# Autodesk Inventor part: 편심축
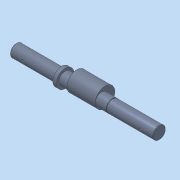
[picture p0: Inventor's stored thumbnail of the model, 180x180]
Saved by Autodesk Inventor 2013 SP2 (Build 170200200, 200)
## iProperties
Manager: 한국ATC센터
Company: 한국ATC센터
Created: 2014-10
Part Number: 편심축
Document SubType Name: Modeling
Designer: 한국ATC센터
Density: 7.86 g/cm^3
Material: 강, 연강
Mass: 1420.77 g
Surface Area: 286.549 cm^2
Volume: 180.76 cm^3
Author: KYOUNG IL JANG
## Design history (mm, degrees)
sketch "스케치1"
  geometry: L1 (-142, 0)-(142, 0); L2 (-142, 0)-(-142, 12.5); L3 (-142, 12.5)-(-52, 12.5); L4 (-52, 12.5)-(-52, 17.5); L5 (-52, 17.5)-(-45, 17.5); L6 (-45, 17.5)-(-45, 12.5); L7 (-45, 12.5)-(48.65, 12.5); L8 (48.65, 12.5)-(48.65, 11.95); L9 (48.65, 11.95)-(50, 11.95); L10 (50, 11.95)-(50, 12.5); L11 (50, 12.5)-(142, 12.5); L12 (142, 12.5)-(142, 0); L13 (109, 12.5)-(109, 9.1); L14 (109, 9.1)-(134, 9.1); L15 (134, 9.1)-(134, 12.5); L16 (117, -12.5)-(119.5, -12.5); L17 (119.5, -12.5)-(117, -10); L18 (117, -10)-(117, -12.5); L19 (-109, 12.5)-(-109, 9.1); L20 (-109, 9.1)-(-134, 9.1); L21 (-134, 9.1)-(-134, 12.5); L22 (-117, -12.5)-(-117, -10); L23 (-117, -10)-(-114.5, -12.5); L24 (-114.5, -12.5)-(-117, -12.5); 2 further points
  constraints: 48 end point, 11 parallel, 8 perpendicular, 5 collinear, 4 point on line, 1 coincident, 1 horizontal, 1 midpoint, 1 vertical
  dimensions: "d0" = 284 distance of L1.start L1.end (derived); "d1" = 25 diameter of L3 L1; "d2" = 35 diameter of L5 L1; "d3" = 90 distance of L2.end L3.end; "d4" = 187 distance between parallel lines of L12 L6; "d6" = 1.35 distance of L8.end L9.end; "d7" = 23.9 diameter of L9 L1; "d8" = 3.4 distance between parallel lines of L14 L11; "d9" = 8 distance between parallel lines of L15 L12; "d10" = 25 distance of L13.end L14.end; "d11" = 25 diameter of L16 L1 (= d1); "d12" = 25 distance from line of L12 L16.start; "d13" = 45 deg angle of L17 L18; "d14" = 5 diameter of L16.end L18; "d27" = 92 distance between parallel lines of L10 L12; "d32" = 7 distance of L4.end L5.end; "d33" = 8 distance between parallel lines of L2 L21; "d34" = 25 distance between parallel lines of L21 L19; "d35" = 3.4 distance between parallel lines of L3 L20; "d36" = 25 distance from line of L22.start L2; "d37" = 5 diameter of L23.end L22
revolve "회전1" stored, may be unused: angle "d15" = 90 deg
revolve "회전2" stored, may be unused: angle "d16" = 90 deg
revolve "회전3" stored, may be unused: angle "d38" = 90 deg
extrude "돌출1" cut sketch "스케치1" stored distance "d17" = 8; taper "d18" = 0 deg
fillet "모깎기1" dims "d19" = 4
node "작업 평면1"
sketch "스케치2"
  geometry: L1 (12.99, -6.5)-(8.66, -14); L2 (-12.99, -6.5)-(-8.66, -14); C1 r 12.5 at (0, 0) reference; C2 r 19.5 at (0, 7); A1 r 15 centre (0, 1) between (12.99, -6.5) and (-12.99, -6.5); A2 r 10 centre (0, -9) between (-8.66, -14) and (8.66, -14); 1 further point
  constraints: 5 tangent, 4 end point, 4 point on circle, 3 centre point, 3 vertical alignment
  dimensions: "d21" = 7 distance of point (0, 0) C2.centre; "d30" = 39 diameter of C2 (derived); "d39" = 10 distance of A2.centre A1.centre; "d40" = 30 diameter of A1; "d41" = 20 diameter of A2; "d42" = 1 distance of point (0, 0) A1.centre
extrude "돌출2" join sketch "스케치2" distance "d22" = 56; taper "d23" = 0 deg
chamfer "모따기1" distance "d24" = 1; stored, may be unused: second distance "d25" = 2, angle "d26" = 45 deg
node "솔리드1"
other parameters: "d20" = 16
